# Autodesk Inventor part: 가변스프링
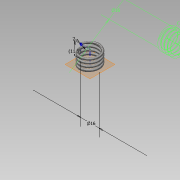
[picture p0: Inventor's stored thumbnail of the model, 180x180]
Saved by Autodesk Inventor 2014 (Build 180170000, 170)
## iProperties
Created: 2015-04
Part Number: 가변스프링
Material: 강철, 탄소
Document SubType Name: Modeling
Designer: Administrator
Density: 7.87 g/cm^3
Appearance: 반연마
Mass: 4.60405 g
Surface Area: 12.8778 cm^2
Volume: 0.585012 cm^3
Author: Administrator
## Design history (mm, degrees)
sketch "스케치1"
  geometry: L1 (0, 0)-(-8, 0); L2 (-8, 0)-(-8, -11.5); L3 (-8, -11.5)-(0, -11.5); L4 (0, -11.5)-(0, 0); C1 r 1 at (-8, 0); 1 further point
  constraints: 8 end point, 2 coincident, 2 parallel, 1 centre point, 1 horizontal, 1 perpendicular
  dimensions: "d0" = 16 diameter of L2 L4; "d1" = 11.50049 distance between parallel lines of L3 L1 (derived); "d2" = 2 diameter of C1
feature "코일1" pitch "d3" = 10; turns "d5" = 4; dims "d4" = 11.50049 (= d1), "d6" = 0, angle "d7" = 90 deg, angle "d8" = 90 deg, "d9" = 0, "d10" = 0
sketch "스케치2"
  geometry: L1 (7, 0)-(9, 0) reference; 1 further point
  constraints: 1 horizontal alignment
extrude "돌출1" cut sketch "스케치2" stored distance "d11" = 10; taper "d12" = 0 deg
node "작업 평면1"
sketch "스케치3"
  geometry: L1 (9, 0)-(7, 0) reference; 1 further point
  constraints: 1 horizontal alignment
extrude "돌출2" cut sketch "스케치3" stored distance "d13" = 10; taper "d14" = 0 deg
node "솔리드1"
node "절단 모서리 투영1"
node "절단 모서리 투영2"
